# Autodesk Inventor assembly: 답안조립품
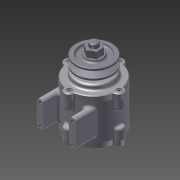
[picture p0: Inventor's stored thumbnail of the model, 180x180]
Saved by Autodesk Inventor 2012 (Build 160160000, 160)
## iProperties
Created: 2015-03
Part Number: 답안조립품
Document SubType Name: Assembly
Designer: Administrator
Author: Administrator
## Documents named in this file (11)
- C:\Documents and Settings\Administrator\바탕 화면\450305V1039\답안조립품.iam
- C:\Documents and Settings\Administrator\바탕 화면\450305V1039\본체.ipt
- C:\Documents and Settings\Administrator\바탕 화면\450305V1039\커버2.ipt
- C:\Documents and Settings\Administrator\바탕 화면\450305V1039\커버.ipt
- C:\Documents and Settings\Administrator\바탕 화면\450305V1039\오일실.ipt
- C:\Documents and Settings\Administrator\바탕 화면\450305V1039\베어링 6204.ipt
- C:\Documents and Settings\Administrator\바탕 화면\450305V1039\축.ipt
- C:\Documents and Settings\Administrator\바탕 화면\450305V1039\키(4 x 4 x 12).ipt
- C:\Documents and Settings\Administrator\바탕 화면\450305V1039\V벨트풀리.ipt
- C:\Documents and Settings\Administrator\바탕 화면\450305V1039\너트 M12x1.25.ipt
- C:\Documents and Settings\Administrator\바탕 화면\450305V1039\M 4 x 12.ipt
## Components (14 placed, 6 different names)
1. KS B 2804 D D - 20 32 8:1
2. KS B 1012 클래스 1 일반 - 미터 M12x1.25:1
3. KS B 2023 6204 - 20 x 47 x 14:3
4. KS B 2023 6204 - 20 x 47 x 14:4
5. KS B 1311 (I) 4 x 4 x 12:1
6. 그루브 풀리1:1
7. KS B 1003 - 미터 M 4 x 12:5
8. KS B 1003 - 미터 M 4 x 12:6
9. KS B 1003 - 미터 M 4 x 12:7
10. KS B 1003 - 미터 M 4 x 12:8
11. KS B 1003 - 미터 M 4 x 12:9
12. KS B 1003 - 미터 M 4 x 12:10
13. KS B 1003 - 미터 M 4 x 12:11
14. KS B 1003 - 미터 M 4 x 12:12
